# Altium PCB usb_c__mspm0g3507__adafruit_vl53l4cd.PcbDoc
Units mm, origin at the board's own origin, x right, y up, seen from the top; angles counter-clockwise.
Board outline 92 x 60 mm, 2 copper layers (Top, Bottom), stack 0 mm thick; 36 components, 29 nets, 192 pads, 58 vias.
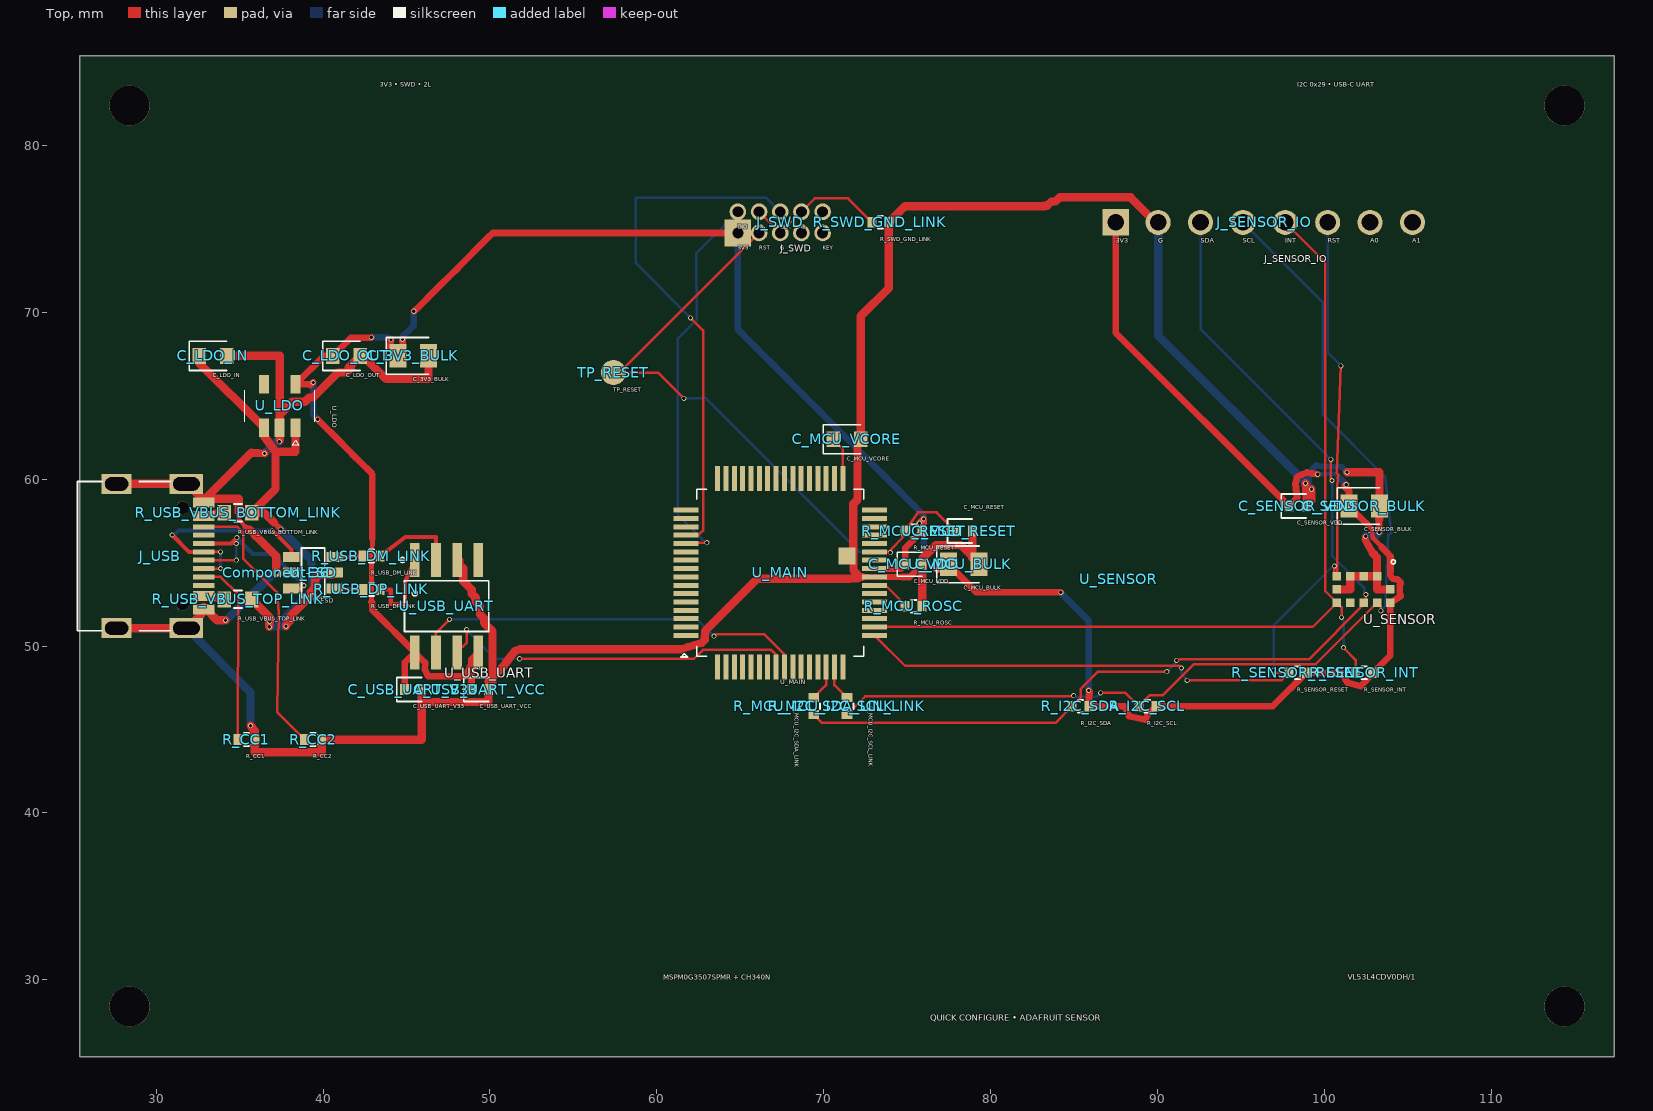
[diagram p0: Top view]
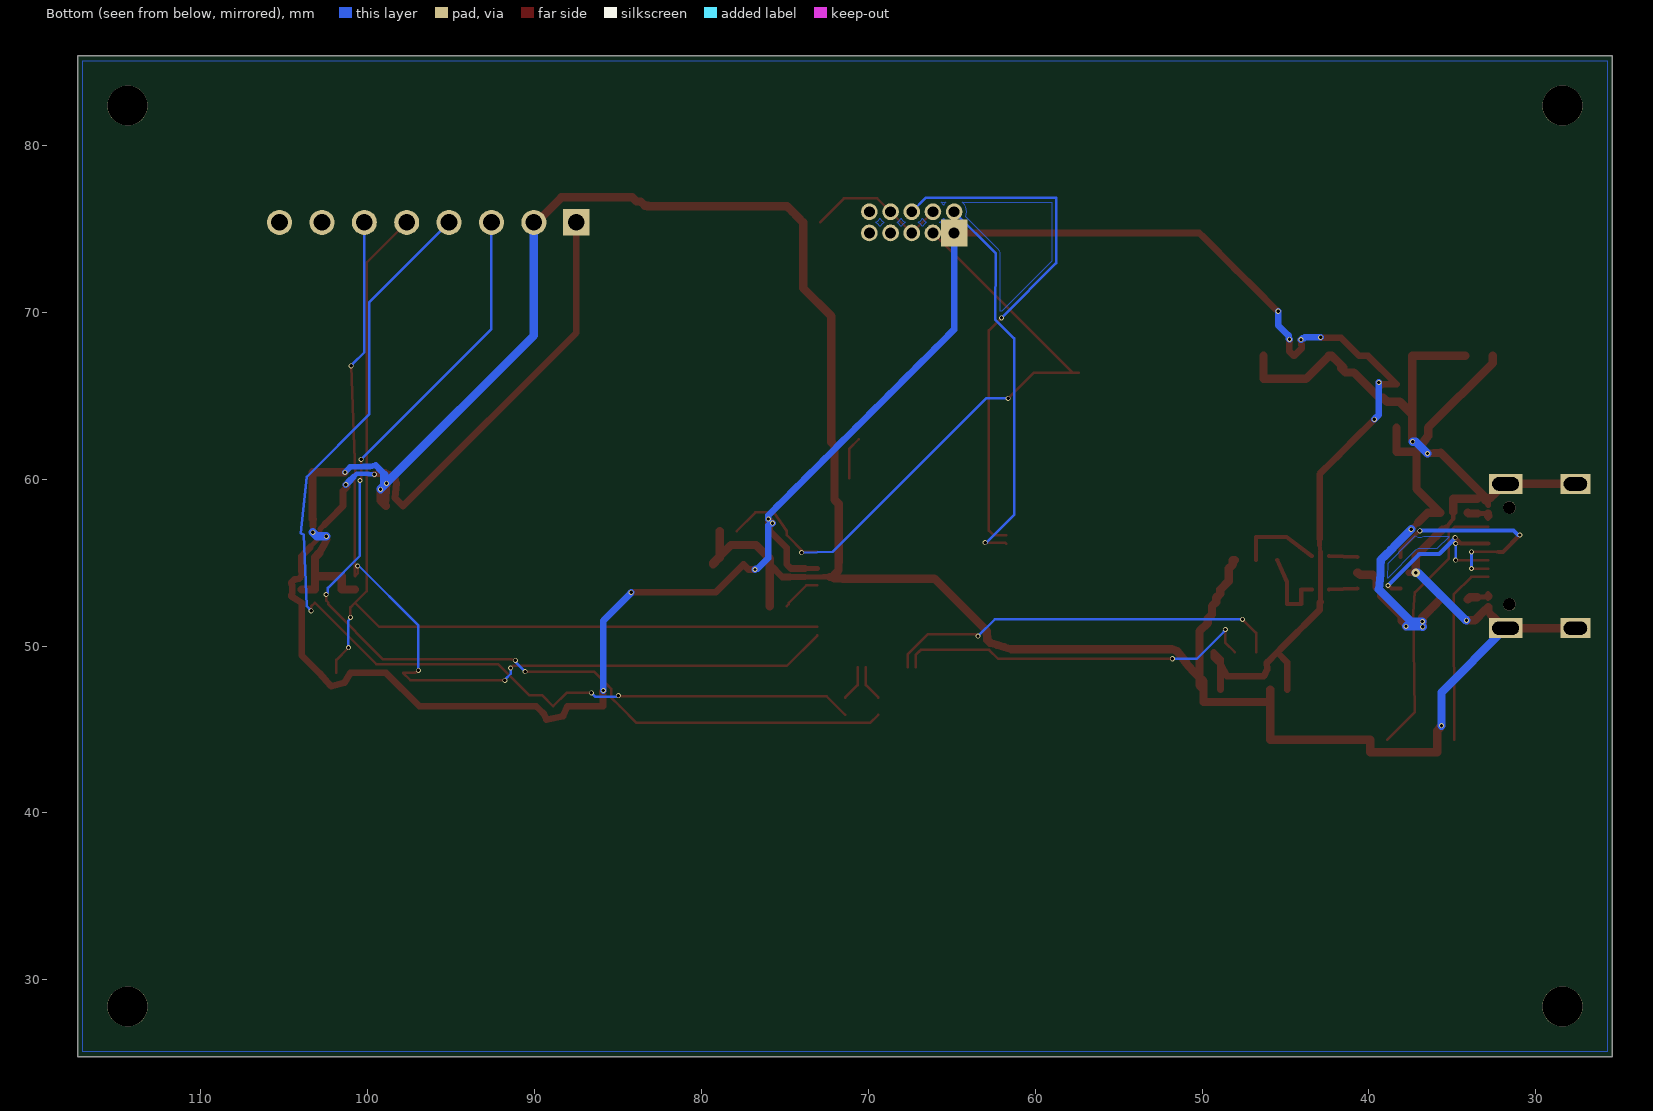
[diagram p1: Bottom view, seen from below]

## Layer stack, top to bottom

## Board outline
25.4,85.4 117.4,85.4 117.4,25.4 25.4,25.4

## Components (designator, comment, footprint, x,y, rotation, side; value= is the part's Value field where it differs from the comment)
C_3V3_BULK "" TSCIRCUIT-2.8500x1.4000mm 45.4,67.4 r0 top
C_LDO_IN "" TSCIRCUIT-2.4500x0.9500mm 33.4,67.4 r0 top
C_LDO_OUT "" TSCIRCUIT-2.4500x0.9500mm 41.4,67.4 r0 top
C_MCU_BULK "" TSCIRCUIT-2.8500x1.4000mm 78.4,54.9 r0 top
C_MCU_RESET "" TSCIRCUIT-1.5600x0.6400mm 78.4,56.9 r0 top
C_MCU_VCORE "" TSCIRCUIT-2.4500x0.9500mm 71.4,62.4 r0 top
C_MCU_VDD "" TSCIRCUIT-1.5600x0.6400mm 75.4,54.9 r0 top
C_SENSOR_BULK "" TSCIRCUIT-2.8500x1.4000mm 102.4,58.4 r0 top
C_SENSOR_VDD "" TSCIRCUIT-1.5600x0.6400mm 98.4,58.4 r0 top
C_USB_UART_V33 "" TSCIRCUIT-1.5600x0.6400mm 45.4,47.4 r0 top
C_USB_UART_VCC "" TSCIRCUIT-1.5600x0.6400mm 49.4,47.4 r0 top
Component-36 "" TSCIRCUIT-0.5000x0.5000mm 37.2,54.4 r0 top
J_SENSOR_IO "" TSCIRCUIT-19.2800x1.5000mm 96.4,75.4 r0 top
J_SWD "" TSCIRCUIT-6.0800x2.2700mm 67.4,75.4 r0 top
J_USB "" TSCIRCUIT-6.7732x9.8502mm 30.113,55.4 r90 top
R_CC1 "" TSCIRCUIT-1.5600x0.6400mm 35.4,44.4 r0 top
R_CC2 "" TSCIRCUIT-1.5600x0.6400mm 39.4,44.4 r0 top
R_I2C_SCL "" TSCIRCUIT-1.5600x0.6400mm 89.4,46.4 r0 top
R_I2C_SDA "" TSCIRCUIT-1.5600x0.6400mm 85.4,46.4 r0 top
R_MCU_I2C_SCL_LINK "" TSCIRCUIT-0.6400x1.5600mm 71.4,46.4 r270 top
R_MCU_I2C_SDA_LINK "" TSCIRCUIT-0.6400x1.5600mm 69.4,46.4 r270 top
R_MCU_RESET "" TSCIRCUIT-1.5600x0.6400mm 75.4,56.9 r0 top
R_MCU_ROSC "" TSCIRCUIT-1.5600x0.6400mm 75.4,52.4 r0 top
R_SENSOR_INT "" TSCIRCUIT-1.5600x0.6400mm 102.4,48.4 r0 top
R_SENSOR_RESET "" TSCIRCUIT-1.5600x0.6400mm 98.4,48.4 r0 top
R_SWD_GND_LINK "" TSCIRCUIT-1.5600x0.6400mm 73.4,75.4 r0 top
R_USB_DM_LINK "" TSCIRCUIT-1.5600x0.6400mm 42.9,55.4 r0 top
R_USB_DP_LINK "" TSCIRCUIT-1.5600x0.6400mm 42.9,53.4 r0 top
R_USB_VBUS_BOTTOM_LINK "" TSCIRCUIT-2.4500x0.9500mm 34.9,58 r0 top
R_USB_VBUS_TOP_LINK "" TSCIRCUIT-2.4500x0.9500mm 34.9,52.8 r0 top
TP_RESET "" TSCIRCUIT-1.5000x1.5000mm 57.4,66.4 r0 top
U_ESD "" TSCIRCUIT-3.6000x2.5000mm 39.4,54.4 r0 top
U_LDO "" TSCIRCUIT-2.5000x3.7000mm 37.4,64.4 r270 top
U_MAIN "" TSCIRCUIT-12.8000x12.8000mm 67.4,54.4 r0 top
U_SENSOR "" TSCIRCUIT-3.7081x2.1079mm 102.368,53.4 r0 top
U_USB_UART "" TSCIRCUIT-4.3840x7.5712mm 47.4,52.4 r0 top

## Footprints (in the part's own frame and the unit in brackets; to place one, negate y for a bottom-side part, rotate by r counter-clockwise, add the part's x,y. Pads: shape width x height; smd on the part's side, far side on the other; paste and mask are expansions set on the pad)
TSCIRCUIT-0.5000x0.5000mm [mm]
TSCIRCUIT-0.6400x1.5600mm [mm]
  rect 0.54x0.64 smd: 1(-0.51,0) 2(0.51,0)
  silkscreen extent -0.15,-0.38 0.15,0.38
TSCIRCUIT-1.5000x1.5000mm [mm]
  round 1.5 smd: 1(0,0)
TSCIRCUIT-1.5600x0.6400mm [mm]
  rect 0.54x0.64 smd: 1(-0.51,0) 2(0.51,0)
  silkscreen extent -0.98,-0.72 0.51,0.72
TSCIRCUIT-2.4500x0.9500mm [mm]
  rect 0.8x0.95 smd: 1(-0.825,0) 2(0.825,0)
  silkscreen extent -1.42,-0.87 0.82,0.87
TSCIRCUIT-2.5000x3.7000mm [mm]
  rect 1.1x0.6 smd: 1(1.3,0.95) 2(1.3,0) 3(1.3,-0.95) 4(-1.3,-0.95) 5(-1.3,0.95)
  silkscreen extent -0.95,-2.1 2.35,2.1
TSCIRCUIT-2.8500x1.4000mm [mm]
  rect 1.025x1.4 smd: 1(-0.913,0) 2(0.913,0)
  silkscreen extent -1.63,-1.1 0.91,1.1
TSCIRCUIT-3.6000x2.5000mm [mm]
  rect 1x0.6 smd: 1(-1.3,-0.95) 2(-1.3,0) 3(-1.3,0.95) 4(1.3,0.95) 5(1.3,0) 6(1.3,-0.95)
  silkscreen extent -0.7,-1.49 0.7,1.49
TSCIRCUIT-3.7081x2.1079mm [mil]
  rect 39.37x39.37 smd: 1(-1219.22,78.75)
  rect 20x20 smd: 2(31.49,31.49) 3(-0.01,31.49) 4(-31.5,31.49) 5(-63,31.49) 6(-63,0.01) 7(-63,-31.49) 8(-31.5,-31.49) 9(-0.01,-31.49) 10(31.49,-31.49) 11(62.99,-31.49) 12(62.99,0.01)
  silkscreen extent 65,60 75,70
TSCIRCUIT-4.3840x7.5712mm [mm]
  rect 0.574x2.036 smd: 1(-1.905,2.768) 2(-0.635,2.768) 3(0.635,2.768) 4(1.905,2.768) 5(1.905,-2.768) 6(0.635,-2.768) 7(-0.635,-2.768) 8(-1.905,-2.768)
  silkscreen extent -2.79,-1.52 2.53,2.92
TSCIRCUIT-6.0800x2.2700mm [mm]
  rect 1.6x1.6 hole 0.65: 1(-2.54,-0.635)
  round 1 hole 0.65: 2(-2.54,0.635) 3(-1.27,0.635) 4(0,0.635) 5(1.27,0.635) 6(2.54,0.635) 7(2.54,-0.635) 8(1.27,-0.635) 9(0,-0.635) 10(-1.27,-0.635)
TSCIRCUIT-6.7732x9.8502mm [mm]
  rect 0.3x1.3 smd: 1(-3.35,-2.737) 2(-3.05,-2.737) 3(-2.55,-2.737) 4(-2.25,-2.737) 5(-1.75,-2.737) 6(-1.25,-2.737) 7(-0.75,-2.737) 8(-0.25,-2.737) 9(0.25,-2.737) 10(0.75,-2.737) 11(1.25,-2.737) 12(1.75,-2.737) 13(2.55,-2.737) 14(2.25,-2.737) 15(3.35,-2.737) 16(3.05,-2.737)
  rect 1.2x2 hole 0.8 slot 1.6 at 90 deg: 17(-4.325,-1.693) 18(4.325,-1.693)
  rect 1.2x1.8 hole 0.8 slot 1.4 at 90 deg: 19(4.325,2.487) 20(-4.325,2.487)
  round 0.75 hole 0.75 unplated: NPTH-1(-2.9,-1.468) NPTH-2(2.9,-1.468)
  silkscreen extent -4.47,-0.75 4.47,4.83
TSCIRCUIT-12.8000x12.8000mm [mm]
  rect 1.5x0.3 smd: 1(-5.65,-3.75) 2(-5.65,-3.25) 3(-5.65,-2.75) 4(-5.65,-2.25) 5(-5.65,-1.75) 6(-5.65,-1.25) 7(-5.65,-0.75) 8(-5.65,-0.25) 9(-5.65,0.25) 10(-5.65,0.75) 11(-5.65,1.25) 12(-5.65,1.75) 13(-5.65,2.25) 14(-5.65,2.75) 15(-5.65,3.25) 16(-5.65,3.75) 33(5.65,3.75) 34(5.65,3.25) 35(5.65,2.75) 36(5.65,2.25) 37(5.65,1.75) 38(5.65,1.25) 39(5.65,0.75) 40(5.65,0.25) 41(5.65,-0.25) 42(5.65,-0.75) 43(5.65,-1.25) 44(5.65,-1.75) 45(5.65,-2.25) 46(5.65,-2.75) 47(5.65,-3.25) 48(5.65,-3.75)
  rect 0.3x1.5 smd: 17(-3.75,5.65) 18(-3.25,5.65) 19(-2.75,5.65) 20(-2.25,5.65) 21(-1.75,5.65) 22(-1.25,5.65) 23(-0.75,5.65) 24(-0.25,5.65) 25(0.25,5.65) 26(0.75,5.65) 27(1.25,5.65) 28(1.75,5.65) 29(2.25,5.65) 30(2.75,5.65) 31(3.25,5.65) 32(3.75,5.65) 49(3.75,-5.65) 50(3.25,-5.65) 51(2.75,-5.65) 52(2.25,-5.65) 53(1.75,-5.65) 54(1.25,-5.65) 55(0.75,-5.65) 56(0.25,-5.65) 57(-0.25,-5.65) 58(-0.75,-5.65) 59(-1.25,-5.65) 60(-1.75,-5.65) 61(-2.25,-5.65) 62(-2.75,-5.65) 63(-3.25,-5.65) 64(-3.75,-5.65)
  silkscreen extent -5.95,-5.05 5,5
TSCIRCUIT-19.2800x1.5000mm [mm]
  rect 1.6x1.6 hole 1: 1(-8.89,0)
  round 1.5 hole 1: 2(-6.35,0) 3(-3.81,0) 4(-1.27,0) 5(1.27,0) 6(3.81,0) 7(6.35,0) 8(8.89,0)

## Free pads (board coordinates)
  round 2.4 hole 2.4 unplated: NPTH-3(28.4,28.4) NPTH-4(114.4,28.4) NPTH-5(28.4,82.4) NPTH-6(114.4,82.4)

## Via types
v1: diameter 0.3, hole 0.2, Top to Bottom, 57 vias
v2: diameter 0.5, hole 0.2, Top to Bottom, 1 vias

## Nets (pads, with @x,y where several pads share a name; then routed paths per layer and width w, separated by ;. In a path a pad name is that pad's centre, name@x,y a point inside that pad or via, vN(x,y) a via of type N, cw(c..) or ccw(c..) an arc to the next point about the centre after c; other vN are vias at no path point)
".J_SWD > .pin2 to .U_MAIN > .pin12": J_SWD.2 U_MAIN.12 | length 23.4
  Top w0.15: U_MAIN.12 61.8,56.2 v1(63,56.2)
  Bottom w0.15: v1(63,56.2) 62.989,56.211 62.913,56.211 61.261,57.863 61.261,58.027 61.262,68.446 62.382,69.559 62.378,73.553 J_SWD.2
".J_SWD > .pin4 to .U_MAIN > .pin13": J_SWD.4 U_MAIN.13 | length 31.7
  Top w0.15: U_MAIN.13 61.752,56.652 62.498,56.652 62.771,56.924 62.771,57.038 62.771,68.929 v1(62.021,69.679)
  Bottom w0.15: v1(62.021,69.679) 61.968,69.732 58.745,72.955 58.745,76.868 66.567,76.868 J_SWD.4
".U_MAIN > .pin42 to .R_MCU_ROSC > .pin1": R_MCU_ROSC.1 U_MAIN.42 | length 2.4
  Top w0.15: U_MAIN.42 73.719,53.65 74.769,52.6 74.769,52.521 R_MCU_ROSC.1
GND: C_3V3_BULK.2 C_LDO_IN.2 C_LDO_OUT.2 C_MCU_BULK.2 C_MCU_RESET.2 C_MCU_VCORE.2 C_MCU_VDD.2 C_SENSOR_BULK.2 C_SENSOR_VDD.2 C_USB_UART_V33.2 C_USB_UART_VCC.2 J_SENSOR_IO.2 J_USB.1 J_USB.2 J_USB.15 J_USB.16 J_USB.17 J_USB.18 J_USB.19 J_USB.20 R_CC1.2 R_CC2.2 R_MCU_ROSC.2 R_SWD_GND_LINK.2 U_ESD.2 U_LDO.2 U_MAIN.41 U_SENSOR.2 U_SENSOR.3 U_SENSOR.4 U_SENSOR.6 U_SENSOR.12 U_USB_UART.3 | length 209.9
  Top w0.25: 34.941,58.037 34.941,57.64 35.139,57.395 35.338,57.15
  Top w0.275: J_USB.16 J_USB.15@33.04,58.641
  Top w0.3: J_USB.1@32.699,51.9 J_USB.1 J_USB.1@32.849,52.2 ; J_USB.15@32.699,58.9 J_USB.15 ; J_USB.2 J_USB.1@32.999,52.2 ; J_USB.16@32.849,58.6 J_USB.15 ; J_USB.15@32.999,58.9 J_USB.15 ; J_USB.15@33.04,58.641 33.231,58.832 33.499,58.832 ; U_MAIN.41@72.662,54.155 U_MAIN.41 ; U_MAIN.41@72.675,54.15 72.769,54.15 72.863,54.15 72.956,54.15 U_MAIN.41 ; U_MAIN.41@73.8,54.15 73.706,54.15 73.612,54.15 73.519,54.15 73.425,54.15 73.331,54.15 73.237,54.15 73.144,54.15 U_MAIN.41
  Top w0.312: 35.338,57.15 35.583,56.998
  Top w0.32: 72.3,54.16 U_MAIN.41@72.662,54.155
  Top w0.325: J_USB.16 J_USB.16@32.849,58.6
  Top w0.329: 72.3,54.157 72.402,54.155 U_MAIN.41@72.675,54.15
  Top w0.35: v1(37.377,62.256) v1@37.4,62.35 ; 102.442,56.392 102.455,56.53 v1(102.488,56.585) ; 103.295,57.211 v1(103.299,56.824)
  Top w0.375: U_MAIN.41@73.8,54.15 74.253,54.15 74.707,54.15
  Top w0.4: 37.2,54.4 U_ESD.2@37.6,54.4 ; 74.707,54.15 75.16,54.15 75.41,54.4 75.66,54.65 C_MCU_VDD.2
  Top w0.425: 102.442,56.392 102.678,55.987 102.913,55.581 ; 103.291,57.597 103.295,57.211
  Top w0.475: 35.583,56.998 35.903,56.678 ; 35.687,61.588 36.088,61.569 v1(36.49,61.551) ; 61.41,49.822 61.429,49.803 61.857,49.94 62.285,50.076 62.713,50.213 ; 71.537,54.048 72.008,54.048 72.275,54.16 72.3,54.16 ; 72.129,54.16 72.3,54.157
  Top w0.5: J_USB.20 J_USB.17 31.874,51.075 32.474,51.675 32.699,51.9 ; J_USB.19 J_USB.18 31.874,59.725 32.474,59.125 32.699,58.9 ; J_USB.1@32.849,52.2 J_USB.2 ; J_USB.1@32.999,52.2 33.655,51.544 v1(34.153,51.544) ; 32.999,58.9 35.687,61.588 ; 33.499,58.832 33.658,58.832 34.086,58.832 34.513,58.832 34.941,58.832 34.941,58.434 34.941,58.037 ; C_LDO_IN.2 37.4,67.4 U_LDO.2 ; v1(35.647,45.232) 35.75,45.129 35.75,45.083 35.91,44.923 R_CC1.2 35.91,43.65 39.91,43.65 R_CC2.2 40.41,44.4 40.91,44.4 45.91,44.4 C_USB_UART_V33.2 45.91,46.65 49.91,46.65 C_USB_UART_VCC.2 ; 35.903,56.678 36.224,56.357 36.545,56.036 36.866,55.715 37.187,55.394 37.187,54.904 37.187,54.413 37.2,54.4 ; v1@37.4,62.35 37.4,62.725 U_LDO.2 ; C_3V3_BULK.2 46.313,66.025 43.775,66.025 42.4,67.4 C_LDO_OUT.2 41.877,67.052 41.53,66.705 41.595,66.705 41.65,66.65 41.4,66.4 40.9,66.4 39.4,64.9 39.15,64.9 38.9,64.65 38.15,64.65 37.4,63.9 U_LDO.2 ; U_USB_UART.3 48.053,55.15 48.15,55.15 48.15,54.9 48.4,54.65 48.4,53.9 48.9,53.4 48.9,53.15 49.15,52.9 49.15,52.65 49.4,52.4 49.4,51.9 49.65,51.65 49.65,51.4 50.15,50.9 50.15,47.65 49.91,47.41 C_USB_UART_VCC.2 ; 61.41,49.822 51.822,49.822 51.494,49.712 51.261,49.402 51.028,49.092 50.795,48.782 50.5,48.488 50.205,48.193 49.91,47.898 C_USB_UART_VCC.2 ; 62.713,50.213 62.869,50.369 62.9,50.9 66.048,54.048 71.537,54.048 ; 72.129,54.16 71.957,54.351 71.786,54.541 71.787,55.037 71.775,55.025 71.775,58.525 72.025,58.775 72.025,62.025 72.225,62.225 C_MCU_VCORE.2 72.225,62.892 72.225,63.384 72.225,63.876 72.225,64.368 72.225,64.86 72.225,65.352 72.225,65.844 72.225,66.336 72.225,66.828 72.225,67.32 72.225,67.812 72.225,68.303 72.225,68.795 72.225,69.287 72.225,69.779 73.91,71.464 R_SWD_GND_LINK.2 74.232,75.722 74.554,76.044 74.876,76.366 74.951,76.366 75.438,76.366 75.925,76.366 76.413,76.366 76.9,76.366 77.387,76.366 77.875,76.366 78.362,76.366 78.849,76.366 79.337,76.366 79.824,76.366 80.311,76.366 80.799,76.366 81.286,76.366 81.773,76.366 82.261,76.366 82.748,76.366 83.235,76.366 83.202,76.4 83.4,76.4 83.65,76.65 83.9,76.65 84.15,76.9 88.4,76.9 89.9,75.4 J_SENSOR_IO.2 ; R_MCU_ROSC.2 C_MCU_VDD.2 75.91,55.243 76.733,56.067 78.233,56.067 79.313,54.988 C_MCU_BULK.2 78.91,55.303 C_MCU_RESET.2 ; v1(98.877,59.755) 98.912,59.327 98.947,58.899 98.981,58.471 C_SENSOR_VDD.2 99.241,58.731 v1(99.241,59.397) ; U_SENSOR.6 101.568,53.4 U_SENSOR.4 U_SENSOR.3 U_SENSOR.2 ; v1(101.37,60.419) 103.313,60.419 C_SENSOR_BULK.2 103.313,57.618 103.291,57.597 ; 102.913,55.581 103.168,55.326 U_SENSOR.2 ; U_SENSOR.12 103.168,53.4 U_SENSOR.2
  Bottom w0.35: 99.525,60.838 99.868,60.767 100.265,60.758 100.663,60.75 101.06,60.742 v1(101.37,60.419)
  Bottom w0.375: 98.962,60.275 99.244,60.556 99.525,60.838
  Bottom w0.4: 98.962,60.275 99.018,60.279
  Bottom w0.5: J_USB.17 35.647,47.234 v1(35.647,45.232) ; v1(34.153,51.544) 34.194,51.585 34.238,51.585 37.053,54.4 37.2,54.4 ; v1(36.49,61.551) 37.195,62.256 v1(37.377,62.256) ; J_SENSOR_IO.2 90.05,68.622 98.849,59.823 99.241,59.431 v1(99.241,59.397) ; v1(98.877,59.755) 99.034,59.708 99.026,59.993 99.018,60.279 ; v1(102.488,56.585) 103.06,56.585 v1(103.299,56.824)
MAIN_RESET: C_MCU_RESET.1 J_SWD.10 R_MCU_RESET.1 TP_RESET.1 U_MAIN.38 | length 40.8
  Top w0.15: v1(61.625,64.85) 61.552,64.923 60.075,66.4 TP_RESET.1 57.765,66.4 J_SWD.10 ; v1(74,55.6) U_MAIN.38 73.889,55.65 74.889,56.651 R_MCU_RESET.1@74.889,56.899 ; R_MCU_RESET.1 75.65,58.014 76.776,58.014 C_MCU_RESET.1
  Bottom w0.15: v1(61.625,64.85) 62.942,64.85 72.142,55.65 v1(74,55.6)
MCU_I2C_SCL_LOCAL: R_MCU_I2C_SCL_LINK.1 U_MAIN.50 | length 2.2
  Top w0.15: U_MAIN.50 70.65,47.66 R_MCU_I2C_SCL_LINK.1
MCU_I2C_SDA_LOCAL: R_MCU_I2C_SDA_LINK.1 U_MAIN.51 | length 2.2
  Top w0.15: R_MCU_I2C_SDA_LINK.1 70.15,47.66 U_MAIN.51
MSPM0_VCORE: C_MCU_VCORE.1 U_MAIN.32 | length 2.6
  Top w0.15: C_MCU_VCORE.1 71.15,61.825 U_MAIN.32
SENSOR_ADDR0: J_SENSOR_IO.7
SENSOR_ADDR1: J_SENSOR_IO.8
SENSOR_INT: J_SENSOR_IO.5 R_SENSOR_INT.1 U_MAIN.47 U_SENSOR.7 | length 57.1
  Top w0.15: U_MAIN.47 99.318,51.15 U_SENSOR.7 ; J_SENSOR_IO.5 100.064,73.004 100.063,53.395 100.066,53.302 U_SENSOR.7 ; v1(101.043,51.723) 101.043,52.325 U_SENSOR.7 ; v1(101.161,49.911) 101.206,49.866 101.89,49.182 R_SENSOR_INT.1
  Bottom w0.15: v1(101.043,51.723) 101.074,51.692 101.074,51.624 101.161,51.537 v1(101.161,49.911)
SENSOR_RESET: J_SENSOR_IO.6 R_SENSOR_RESET.1 U_MAIN.48 U_SENSOR.5 | length 57.4
  Top w0.15: U_MAIN.48 74.889,48.811 91.288,48.811 91.31,48.811 v1(91.435,48.686) ; v1(91.791,47.955) 97.445,47.955 R_SENSOR_RESET.1 97.184,48.4 97.153,48.431 97.094,48.431 v1(96.972,48.553) ; v1(100.608,54.803) 100.612,54.356 U_SENSOR.5 100.779,54.211 100.779,59.643 100.855,60.297 100.763,60.35 v1(101,66.8)
  Bottom w0.15: v1(91.435,48.686) 91.435,48.346 91.724,48.057 91.724,48.022 v1(91.791,47.955) ; v1(96.972,48.553) 96.972,51.248 100.542,54.818 100.601,54.818 v1(100.608,54.803) ; J_SENSOR_IO.6 100.21,67.613 100.891,66.932 100.891,66.909 v1(101,66.8)
SENSOR_SCL: J_SENSOR_IO.4 R_I2C_SCL.1 R_MCU_I2C_SCL_LINK.2 U_SENSOR.10 | length 62.9
  Top w0.15: R_MCU_I2C_SCL_LINK.2 72.494,46.984 84.935,46.984 v1(84.982,47.031) ; v1(86.6,47.2) 88.09,47.2 R_I2C_SCL.1 89.541,47.051 89.619,47.051 90.311,47.051 92.189,48.929 99.497,48.929 U_SENSOR.10 103.398,52.37 v1(103.398,52.116)
  Bottom w0.15: v1(84.982,47.031) 85.048,46.961 86.202,46.954 86.365,46.965 86.599,47.199 v1(86.6,47.2) ; J_SENSOR_IO.4 99.921,70.609 99.921,63.885 103.663,60.143 104.009,56.768 103.827,56.674 103.663,52.421 103.663,52.395 103.505,52.237 103.505,52.223 v1(103.398,52.116)
SENSOR_SDA: J_SENSOR_IO.3 R_I2C_SDA.1 R_MCU_I2C_SDA_LINK.2 U_SENSOR.9 | length 63.5
  Top w0.15: R_MCU_I2C_SDA_LINK.2 69.891,45.399 83.889,45.399 R_I2C_SDA.1 85.419,46.929 85.419,47.445 85.584,47.61 86.444,48.47 v1(90.566,48.47) ; v1(91.157,49.153) 91.193,49.189 91.342,49.189 91.363,49.211 99.082,49.211 102.368,52.497 U_SENSOR.9 102.5,52.732 v1(102.5,53.1) ; v1(100.404,61.196) 100.399,60.032 100.459,59.972 100.459,59.962 v1(100.472,59.929)
  Bottom w0.15: v1(90.566,48.47) 90.692,48.596 90.695,48.596 91.157,49.058 v1(91.157,49.153) ; J_SENSOR_IO.3 92.59,69.01 100.269,61.331 100.269,61.326 v1(100.404,61.196) ; v1(100.472,59.929) 100.475,55.417 102.391,53.497 102.39,53.247 102.39,53.21 v1(102.5,53.1)
swd-ground-1-to-2: J_SWD.3 J_SWD.5 J_SWD.9 R_SWD_GND_LINK.1 | length 8.8
  Top w0.15: J_SWD.3 J_SWD.9 J_SWD.5 69.481,76.846 71.471,76.846 71.471,76.819 R_SWD_GND_LINK.1
UART_MSP_RX: U_MAIN.57 U_USB_UART.6 | length 22
  Top w0.15: U_USB_UART.6 48.6,50.197 v1(48.6,51) ; v1(51.78,49.245) 51.82,49.245 62.224,49.245 62.76,49.781 66.857,49.781 66.965,49.673 67.15,49.488 U_MAIN.57
  Bottom w0.15: v1(48.6,51) 48.697,50.903 48.697,50.852 50.304,49.245 v1(51.78,49.245)
UART_MSP_TX: U_MAIN.56 U_USB_UART.7 | length 24.1
  Top w0.15: U_USB_UART.7 46.765,50.794 v1(47.579,51.608) ; v1(63.428,50.6) 63.46,50.632 63.482,50.632 63.558,50.708 66.449,50.708 67.65,49.508 U_MAIN.56
  Bottom w0.15: v1(47.579,51.608) 47.586,51.615 47.757,51.615 62.413,51.615 v1(63.428,50.6)
usb-dm-device: R_USB_DM_LINK.1 U_ESD.4 | length 1.7
  Top w0.25: U_ESD.4 R_USB_DM_LINK.1
usb-dm-port-tie: J_USB.7 J_USB.9 U_ESD.3 | length 13.5
  Top w0.15: J_USB.9@32.349,55.65 32.38,55.65 32.474,55.65 32.568,55.65 32.662,55.65 32.755,55.65 J_USB.9 v1(33.85,55.65) ; J_USB.7 v1(33.85,54.65)
  Top w0.175: J_USB.9@32.287,55.65 J_USB.9@32.349,55.65
  Top w0.212: 32.193,55.65 J_USB.9@32.287,55.65
  Top w0.25: v1(30.956,56.662) 31.968,55.65 32.099,55.65 32.193,55.65 ; v1(36.949,56.916) 36.994,56.89 38.1,55.784 U_ESD.3
  Bottom w0.15: v1(33.85,54.65) v1(33.85,55.65)
  Bottom w0.25: v1(30.956,56.662) 31.07,56.662 31.332,56.924 v1(36.949,56.916)
usb-dm-uart: R_USB_DM_LINK.2 U_USB_UART.2 | length 5.1
  Top w0.25: R_USB_DM_LINK.2 44.95,56.55 46.765,56.55 U_USB_UART.2
usb-dp-device: R_USB_DP_LINK.1 U_ESD.6 | length 1.7
  Top w0.25: U_ESD.6 R_USB_DP_LINK.1
usb-dp-port-tie: J_USB.8 J_USB.10 U_ESD.1 | length 13.1
  Top w0.15: J_USB.8 v1(34.8,55.15) ; J_USB.10 v1(34.8,56.15)
  Top w0.25: J_USB.10 34.477,56.15 v1(34.831,56.504) ; U_ESD.1 38.65,53.45 38.791,53.591 38.859,53.591 v1(38.857,53.635)
  Bottom w0.15: v1(34.8,55.15) v1(34.8,56.15)
  Bottom w0.25: v1(34.831,56.504) 34.9,56.435 34.9,56.406 35.783,55.522 36.978,55.522 v1(38.857,53.635)
usb-dp-uart: R_USB_DP_LINK.2 U_USB_UART.1 | length 5.1
  Top w0.25: R_USB_DP_LINK.2 44.05,53.4 44.05,52.53 44.9,52.53 44.9,53.85 U_USB_UART.1
USB_CC1: J_USB.6 R_CC1.1 | length 11.2
  Top w0.15: J_USB.6 33.853,54.155 34.902,53.121 R_CC1.1
USB_CC2: J_USB.12 R_CC2.1 | length 16.4
  Top w0.15: J_USB.12 34.863,57.15 35.206,56.807 35.206,55.248 37.238,53.216 37.339,52.022 37.238,46.052 R_CC2.1
USB_VBUS_BOTTOM_LOCAL: J_USB.13 J_USB.14 R_USB_VBUS_BOTTOM_LINK.1 | length 1.5
  Top w0.3: J_USB.14 J_USB.14@32.849,57.8 ; J_USB.13 32.927,57.95 33.005,57.95 33.083,57.95 33.161,57.95 33.239,57.95 33.317,57.95 33.394,57.95 33.472,57.95 33.499,57.95
  Top w0.475: J_USB.13@32.849,57.8 J_USB.13 ; 33.499,57.95 R_USB_VBUS_BOTTOM_LINK.1@33.762,57.95
  Top w0.5: R_USB_VBUS_BOTTOM_LINK.1@33.762,57.95 34.025,57.95 R_USB_VBUS_BOTTOM_LINK.1
USB_VBUS_TOP_LOCAL: J_USB.3 J_USB.4 R_USB_VBUS_TOP_LINK.1 | length 1.6
  Top w0.3: J_USB.4 32.849,53 J_USB.3 32.944,52.959 33.033,52.939 33.499,52.939
  Top w0.5: 33.499,52.939 33.675,52.939 33.936,52.939 R_USB_VBUS_TOP_LINK.1
VBUS5: C_LDO_IN.1 R_USB_VBUS_BOTTOM_LINK.2 R_USB_VBUS_TOP_LINK.2 U_ESD.5 U_LDO.1 U_LDO.3 | length 35.8
  Top w0.35: 37.06,57.408 37.466,57.002 v1(37.466,56.999)
  Top w0.5: C_LDO_IN.1 32.575,66.975 U_LDO.3 ; v1(36.778,51.16) 36.778,51.454 36.778,51.747 36.427,52.098 36.076,52.449 R_USB_VBUS_TOP_LINK.2 36.8,51.725 v1(36.8,51.475) ; 37.06,57.408 36.764,57.704 36.76,57.704 36.464,58 R_USB_VBUS_BOTTOM_LINK.2 37.15,59.425 37.15,61.65 ; v1(37.774,51.19) v1(37.774,51.19) 37.775,51.275 38.025,51.525 38.025,51.775 39.275,53.025 39.275,53.275 39.525,53.525 39.525,54.025 39.775,54.275 40.525,54.275 40.65,54.4 U_ESD.5 ; U_LDO.1 38.35,61.65 37.15,61.65 ; U_LDO.3 36.448,62.848 36.446,62.597 37.15,61.65 ; U_LDO.3 36.461,62.639 37.15,61.65
  Bottom w0.5: v1(36.778,51.16) 36.78,51.159 36.789,51.159 36.82,51.19 37.297,51.19 v1(37.774,51.19) ; v1(36.8,51.475) 37.475,51.475 39.4,53.4 39.308,54.328 39.302,54.747 39.295,55.165 38.99,55.471 38.686,55.776 38.381,56.082 38.076,56.387 37.771,56.693 v1(37.466,56.999)
VCC_3V3: C_3V3_BULK.1 C_LDO_OUT.1 C_MCU_BULK.1 C_MCU_VDD.1 C_SENSOR_BULK.1 C_SENSOR_VDD.1 C_USB_UART_V33.1 C_USB_UART_VCC.1 J_SENSOR_IO.1 J_SWD.1 R_I2C_SCL.2 R_I2C_SDA.2 R_MCU_RESET.2 R_SENSOR_INT.2 R_SENSOR_RESET.2 U_LDO.5 U_MAIN.40 U_SENSOR.1 U_SENSOR.11 U_USB_UART.5 U_USB_UART.8 | length 169.5
  Top w0.092: 103.969,54.254 103.968,54.2 104.014,54.154
  Top w0.128: 104.114,54.054 104.157,54.011 104.286,54.005
  Top w0.25: 42.9,55.65 42.925,55.859 42.95,56.068
  Top w0.275: 42.9,53.025 42.9,53.4 42.9,53.775 42.9,54.15 ; 42.9,54.9 42.9,55.275 42.9,55.65 ; 102.865,57.016 102.889,56.758 102.912,56.501 103.179,56.223
  Top w0.288: 42.9,52.65 42.9,53.025 ; 42.9,54.15 42.9,54.525 42.9,54.9 ; 103.179,56.223 103.446,55.945
  Top w0.3: 42.95,56.068 42.951,56.454 ; U_MAIN.40 73.15,54.65 73.25,54.65 73.35,54.65 73.45,54.65 73.55,54.65 73.65,54.65 73.75,54.65 U_MAIN.40@73.8,54.65
  Top w0.312: 102.589,57.293 102.865,57.016
  Top w0.4: v1(39.4,65.8) 39.25,65.65 39.224,65.65 39.174,65.7 38.899,65.7 38.625,65.7 U_LDO.5 40.05,67.4 C_LDO_OUT.1 41.663,68.488 42.876,68.5 v1(42.889,68.512) ; v1(39.673,63.596) 39.946,63.322 40.22,63.049 40.493,62.775 40.766,62.501 41.04,62.228 41.313,61.954 41.586,61.68 41.86,61.407 42.133,61.133 42.407,60.86 42.68,60.586 42.953,60.312 42.953,59.926 42.953,59.541 42.952,59.155 42.952,58.769 42.952,58.383 42.952,57.997 42.951,57.611 42.951,57.226 42.951,56.84 42.951,56.454 ; 42.9,52.65 42.948,52.596 42.948,52.21 42.957,52.17 43.239,51.888 43.521,51.606 43.803,51.324 44.085,51.042 44.367,50.76 44.649,50.478 44.931,50.196 45.213,49.914 U_USB_UART.8 ; v1(44.072,68.366) 44.017,67.871 C_3V3_BULK.1 44.634,67.546 44.781,67.693 44.768,68.039 v1(44.755,68.386) ; C_USB_UART_V33.1 44.89,49.027 U_USB_UART.8 ; v1(45.438,70.073) 45.494,70.129 45.53,70.129 45.803,70.402 46.076,70.675 46.348,70.947 46.621,71.22 46.894,71.493 47.166,71.765 47.439,72.038 47.712,72.311 47.984,72.584 48.257,72.856 48.53,73.129 48.802,73.402 49.075,73.674 49.348,73.947 49.621,74.22 49.893,74.492 50.166,74.765 50.563,74.765 50.96,74.765 51.357,74.765 51.754,74.765 52.152,74.765 52.549,74.765 52.946,74.765 53.343,74.765 53.74,74.765 54.137,74.765 54.534,74.765 54.932,74.765 55.329,74.765 55.726,74.765 56.123,74.765 56.52,74.765 56.917,74.765 57.314,74.765 57.712,74.765 58.109,74.765 58.506,74.765 58.903,74.765 59.3,74.765 59.697,74.765 60.094,74.765 60.491,74.765 60.889,74.765 61.286,74.765 61.683,74.765 62.08,74.765 62.477,74.765 62.874,74.765 63.271,74.765 63.669,74.765 64.066,74.765 64.463,74.765 J_SWD.1 ; C_USB_UART_VCC.1 48.89,49.217 U_USB_UART.5 49.305,49.345 49.093,49.129 48.881,48.912 48.5,48.2 46.3,48.2 46.1,48.6 46.115,49.012 45.908,49.219 45.702,49.425 U_USB_UART.8 ; U_MAIN.40@73.8,54.65 73.85,54.65 74.64,54.65 C_MCU_VDD.1 74.89,55.88 R_MCU_RESET.2 ; v1(75.75,57.375) 75.994,57.614 75.91,57.53 75.91,57.215 R_MCU_RESET.2 ; v1(76,57.62) 76,57.305 76,56.99 R_MCU_RESET.2 ; v1(76.791,54.592) 77.18,54.592 77.334,54.746 C_MCU_BULK.1 79.162,53.226 v1(84.215,53.226) ; v1(85.882,47.346) 85.96,47.253 85.96,47.129 85.91,47.08 R_I2C_SDA.2 86.264,46.4 86.619,46.4 86.973,46.4 87.327,46.4 87.682,46.4 88.036,46.4 88.3,45.8 89.3,45.6 89.482,45.972 ; J_SENSOR_IO.1 87.51,68.78 C_SENSOR_VDD.1 98.129,58.639 98.368,58.878 98.34,59.171 98.312,59.464 98.283,59.757 98.34,59.96 98.396,60.162 98.678,60.283 98.96,60.405 99.288,60.35 v1(99.615,60.295) ; v1(101.314,59.679) 101.244,59.609 101.244,59.549 101.488,59.306 101.488,59.004 101.488,58.702 C_SENSOR_BULK.1 101.763,58.123 102.038,57.846 102.314,57.569 102.589,57.293 ; 103.446,55.945 103.713,55.666 103.98,55.388 103.976,54.992 103.972,54.596 103.969,54.254 ; 104.014,54.154 104.114,54.054 ; 104.286,54.005 104.4,54 104.6,53.8 104.536,53.614 104.536,53.391 104.536,53.168 104.6,53 U_SENSOR.11 103.968,49.458 R_SENSOR_INT.2 102.2,47.6 101.4,47.8 101.036,48.4 100.682,48.4 100.327,48.4 99.973,48.4 99.619,48.4 99.264,48.4 R_SENSOR_RESET.2 96.91,46.4 R_I2C_SCL.2 89.696,46.186 89.482,45.972 ; 89.482,45.972 89.474,45.972 89.482,45.972
  Bottom w0.275: 99.963,60.323 100.311,60.329 100.658,60.335 100.877,60.116
  Bottom w0.3: v1(99.615,60.295) 99.963,60.323
  Bottom w0.387: 100.877,60.116 101.095,59.898 v1(101.314,59.679)
  Bottom w0.4: v1(39.4,65.8) 39.4,65.414 39.4,65.028 39.4,64.641 39.4,64.255 39.4,63.869 39.624,63.645 v1(39.673,63.596) ; v1(42.889,68.512) 43.839,68.501 43.882,68.458 43.979,68.458 v1(44.072,68.366) ; v1(44.755,68.386) 44.795,68.425 44.795,68.59 45.009,68.805 45.224,69.019 45.438,69.233 45.438,69.513 45.438,69.793 v1(45.438,70.073) ; J_SWD.1 64.86,74.379 64.86,73.993 64.86,73.608 64.86,73.222 64.86,72.836 64.86,72.45 64.86,72.065 64.86,71.679 64.86,71.293 64.86,70.907 64.86,70.521 64.86,70.136 64.86,69.75 64.86,69.364 64.86,68.978 65.138,68.7 65.417,68.421 65.695,68.143 65.974,67.864 66.252,67.586 66.531,67.308 66.809,67.029 67.088,66.751 67.366,66.472 67.644,66.194 67.923,65.915 68.201,65.637 68.48,65.358 68.758,65.08 69.037,64.802 69.315,64.523 69.594,64.245 69.872,63.966 70.151,63.688 70.429,63.409 70.707,63.131 70.986,62.852 71.264,62.574 71.543,62.295 71.821,62.017 72.1,61.739 72.378,61.46 72.657,61.182 72.935,60.903 73.213,60.625 73.492,60.346 73.77,60.068 74.049,59.789 74.327,59.511 74.606,59.233 74.884,58.954 75.163,58.676 75.441,58.397 75.719,58.119 75.998,57.84 75.998,57.622 v1(76,57.62) ; v1(75.75,57.375) 76,57.23 76,56.84 76,56.45 76,56.06 76,55.67 76,55.28 76.214,55.066 76.428,54.851 76.643,54.637 76.745,54.637 v1(76.791,54.592) ; v1(84.215,53.226) 84.258,53.183 84.258,53.157 85.882,51.532 v1(85.882,47.346)
pads on no net: J_SWD.6 J_SWD.7 J_SWD.8 J_USB.5 J_USB.11 J_USB.NPTH-1 J_USB.NPTH-2 U_LDO.4 U_MAIN.1 U_MAIN.2 U_MAIN.3 U_MAIN.4 U_MAIN.5 U_MAIN.6 U_MAIN.7 U_MAIN.8 U_MAIN.9 U_MAIN.10 U_MAIN.11 U_MAIN.14 U_MAIN.15 U_MAIN.16 U_MAIN.17 U_MAIN.18 U_MAIN.19 U_MAIN.20 U_MAIN.21 U_MAIN.22 U_MAIN.23 U_MAIN.24 U_MAIN.25 U_MAIN.26 U_MAIN.27 U_MAIN.28 U_MAIN.29 U_MAIN.30 U_MAIN.31 U_MAIN.33 U_MAIN.34 U_MAIN.35 U_MAIN.36 U_MAIN.37 U_MAIN.39 U_MAIN.43 U_MAIN.44 U_MAIN.45 U_MAIN.46 U_MAIN.49 U_MAIN.52 U_MAIN.53 U_MAIN.54 U_MAIN.55 U_MAIN.58 U_MAIN.59 U_MAIN.60 U_MAIN.61 U_MAIN.62 U_MAIN.63 U_MAIN.64 U_SENSOR.8 U_USB_UART.4
copper on no net:
  other v2: 37.2,54.4

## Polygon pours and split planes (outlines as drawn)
GND on Bottom (solid): 117.1,85.1 25.7,85.1 25.7,25.7 117.1,25.7
GND on Bottom (solid): 65.633,76.593 65.357,76.593 65.39,76.565 65.484,76.452 65.495,76.43 65.506,76.452 65.6,76.565
GND on Bottom (solid): 65.495,75.64 65.484,75.618 65.399,75.515 65.591,75.515 65.506,75.618
GND on Bottom (solid): 65.61,75.496 65.61,75.304 65.713,75.389 65.735,75.4 65.713,75.411
GND on Bottom (solid): 69.305,75.64 69.294,75.618 69.2,75.505 69.087,75.411 69.065,75.4 69.087,75.389 69.2,75.295 69.294,75.182 69.305,75.16 69.316,75.182 69.41,75.295 69.523,75.389 69.545,75.4 69.523,75.411 69.41,75.505 69.316,75.618
GND on Bottom (solid): 68.035,75.64 68.024,75.618 67.93,75.505 67.817,75.411 67.795,75.4 67.817,75.389 67.93,75.295 68.024,75.182 68.035,75.16 68.046,75.182 68.14,75.295 68.253,75.389 68.275,75.4 68.253,75.411 68.14,75.505 68.046,75.618
GND on Bottom (solid): 66.765,75.64 66.754,75.618 66.66,75.505 66.547,75.411 66.525,75.4 66.547,75.389 66.66,75.295 66.754,75.182 66.765,75.16 66.776,75.182 66.87,75.295 66.983,75.389 67.005,75.4 66.983,75.411 66.87,75.505 66.776,75.618
GND on Bottom (solid): 64.363,76.593 59.02,76.593 59.02,73.069 62.011,70.078 62.021,70.079 62.099,70.071 62.107,70.069 62.103,73.552 62.103,73.553 62.108,73.606 62.123,73.658 62.149,73.705 62.183,73.747 64.173,75.737 64.167,75.748 64.124,75.889 64.11,76.035 64.124,76.181 64.167,76.322 64.236,76.452 64.33,76.565
GND on Bottom (solid): 37.211,56.616 37.171,56.584 37.102,56.547 37.027,56.524 36.949,56.516 36.871,56.524 36.796,56.547 36.727,56.584 36.717,56.592 35.22,56.594 35.223,56.582 35.228,56.538 35.918,55.847 36.978,55.847 37.041,55.841 37.102,55.823 37.158,55.793 37.207,55.752 37.208,55.752 38.881,54.071 38.86,54.283 38.862,54.284 38.858,54.321 38.852,54.74 38.848,54.976 38.672,55.152 38.672,55.153 38.367,55.458 38.062,55.764 37.757,56.069 37.757,56.07 37.452,56.375

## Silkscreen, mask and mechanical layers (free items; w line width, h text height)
Top Overlay:
  text "3V3 • SWD • 2L" at 43.4,83.4 h0.48
  text "I2C 0x29 • USB-C UART" at 98.4,83.4 h0.5
  text "MSPM0G3507SPMR + CH340N" at 60.4,29.9 h0.52
  text "VL53L4CDV0DH/1" at 101.4,29.9 h0.55
  text "QUICK CONFIGURE • ADAFRUIT SENSOR" at 76.4,27.4 h0.65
